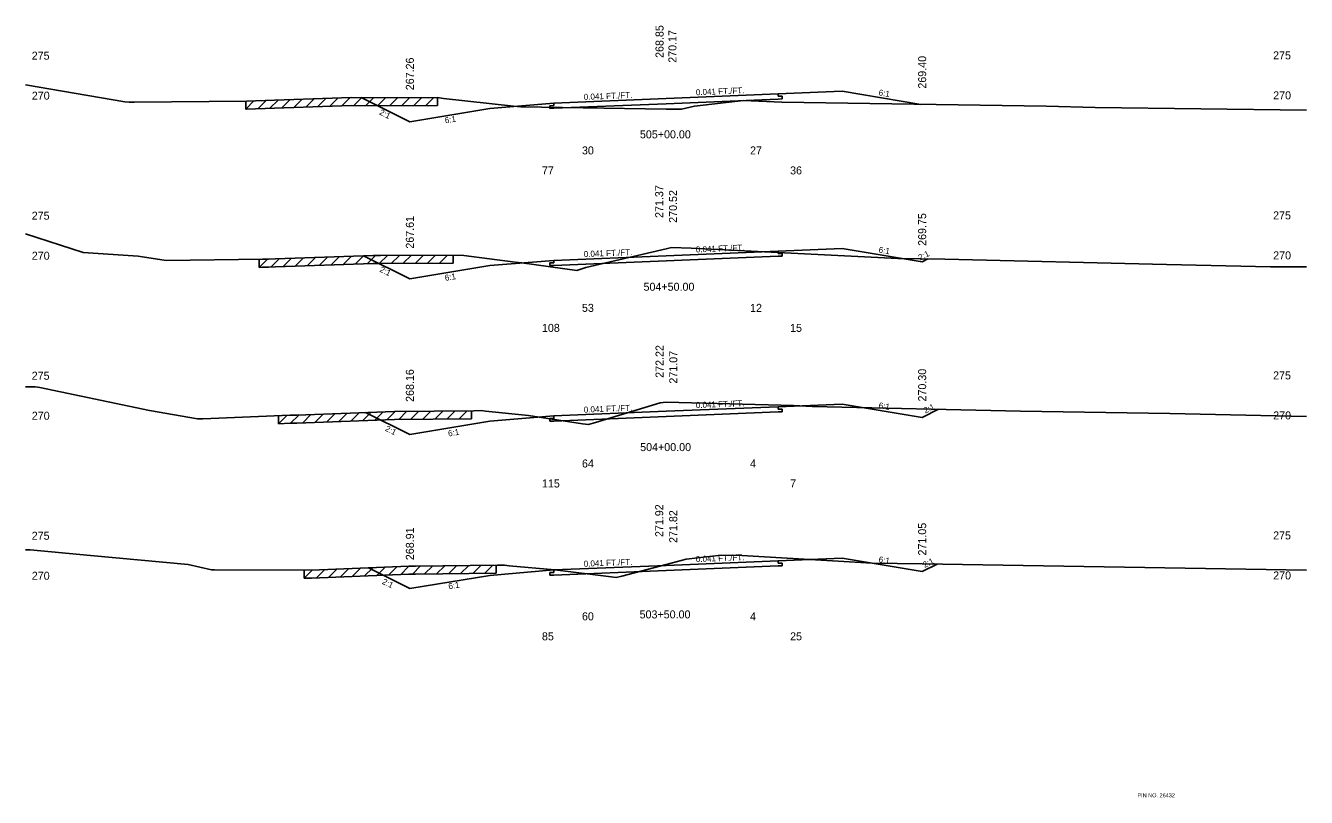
# Model space of a CAD drawing. Extents: x 2967 to 4323, y -3677 to -817.
# Drawn here: x 3188.8 to 3348.8, y -2657 to -2560.6 of the extents above; entities that cross this region are included whole.
import ezdxf

# ---------------------------------------------------------------- set-up
doc = ezdxf.new("R2010")
doc.units = 0
for name, color, linetype in [('Level 1', 7, 'Continuous'), ('Level 10', 7, 'Continuous'), ('Level 11', 7, 'Continuous'), ('Level 12', 7, 'Continuous'), ('Level 20', 7, 'Continuous'), ('Level 3', 7, 'Continuous'), ('Level 32', 7, 'Continuous'), ('Level 33', 7, 'Continuous'), ('Level 59', 7, 'Continuous'), ('Level 6', 7, 'Continuous'), ('Level 60', 7, 'Continuous'), ('Level 61', 7, 'Continuous'), ('Level 7', 7, 'Continuous')]:
    doc.layers.add(name, color=color, linetype=linetype)

msp = doc.modelspace()

# ---------------------------------------------------------------- linework, layer by layer
at = {"layer": 'Level 11'}
for p, q in [((3282.76, -2569.4), (3282.76, -2569.1)), ((3283.26, -2569.38), (3282.76, -2569.4)), ((3283.26, -2569.72), (3283.26, -2569.38)), ((3254.76, -2570.55), (3254.26, -2570.57)), ((3254.26, -2570.57), (3254.26, -2570.91)), ((3254.26, -2570.91), (3254.76, -2570.89)), ((3254.76, -2570.25), (3254.76, -2570.55)), ((3282.76, -2569.74), (3283.26, -2569.72)), ((3282.76, -2589.05), (3282.76, -2588.75)), ((3254.76, -2590.2), (3254.26, -2590.22)), ((3254.26, -2590.22), (3254.26, -2590.56)), ((3254.76, -2589.9), (3254.76, -2590.2)), ((3283.26, -2589.03), (3282.76, -2589.05)), ((3282.76, -2589.39), (3283.26, -2589.37)), ((3283.26, -2589.37), (3283.26, -2589.03)), ((3254.26, -2590.56), (3254.76, -2590.54)), ((3254.76, -2609.35), (3254.76, -2609.65)), ((3282.76, -2608.5), (3282.76, -2608.2)), ((3283.26, -2608.48), (3282.76, -2608.5)), ((3282.76, -2608.84), (3283.26, -2608.82)), ((3283.26, -2608.82), (3283.26, -2608.48)), ((3254.76, -2609.65), (3254.26, -2609.67)), ((3254.26, -2609.67), (3254.26, -2610.01)), ((3254.26, -2610.01), (3254.76, -2609.99)), ((3254.76, -2628.6), (3254.76, -2628.9)), ((3282.76, -2627.75), (3282.76, -2627.45)), ((3283.26, -2627.73), (3282.76, -2627.75)), ((3282.76, -2628.09), (3283.26, -2628.07)), ((3283.26, -2628.07), (3283.26, -2627.73)), ((3254.76, -2628.9), (3254.26, -2628.92)), ((3254.26, -2628.92), (3254.26, -2629.26)), ((3254.26, -2629.26), (3254.76, -2629.24))]:
    msp.add_line(p, q, dxfattribs=at)
at = {"layer": 'Level 12'}
for p, q in [((3268.76, -2570.32), (3254.76, -2570.89)), ((3282.76, -2569.74), (3268.76, -2570.32)), ((3268.76, -2589.96), (3254.76, -2590.54)), ((3282.76, -2589.39), (3268.76, -2589.96)), ((3268.76, -2609.41), (3254.76, -2609.99)), ((3282.76, -2608.84), (3268.76, -2609.41)), ((3268.76, -2628.67), (3254.76, -2629.24)), ((3282.76, -2628.09), (3268.76, -2628.67))]:
    msp.add_line(p, q, dxfattribs=at)
at = {"layer": 'Level 59'}
for p, q in [((3268.76, -2569.68), (3282.76, -2569.1)), ((3254.76, -2570.25), (3268.76, -2569.68)), ((3268.76, -2589.32), (3282.76, -2588.75)), ((3254.76, -2589.9), (3268.76, -2589.32)), ((3254.76, -2609.35), (3268.76, -2608.77)), ((3268.76, -2608.77), (3282.76, -2608.2)), ((3254.76, -2628.6), (3268.76, -2628.03)), ((3268.76, -2628.03), (3282.76, -2627.45))]:
    msp.add_line(p, q, dxfattribs=at)
at = {"layer": 'Level 6'}
for p, q in [((3282.76, -2569.1), (3290.76, -2568.77)), ((3246.76, -2570.92), (3254.76, -2570.25)), ((3282.76, -2588.75), (3290.76, -2588.42)), ((3246.76, -2590.56), (3254.76, -2589.9)), ((3282.76, -2608.2), (3290.76, -2607.87)), ((3246.76, -2610.01), (3254.76, -2609.35)), ((3282.76, -2627.45), (3290.76, -2627.12)), ((3246.76, -2629.27), (3254.76, -2628.6))]:
    msp.add_line(p, q, dxfattribs=at)
at = {"layer": 'Level 60'}
for p, q in [((3188.76, -2567.98), (3201.17, -2570.1)), ((3217.46, -2569.96), (3229.42, -2569.53)), ((3229.42, -2569.53), (3239.11, -2569.57)), ((3239.11, -2569.57), (3240.21, -2569.56)), ((3240.21, -2569.56), (3240.96, -2569.66)), ((3201.17, -2570.1), (3201.71, -2570.14)), ((3201.71, -2570.14), (3202.31, -2570.13)), ((3202.31, -2570.13), (3216.34, -2570)), ((3216.34, -2570), (3217.46, -2569.96)), ((3240.96, -2569.66), (3249.7, -2570.61)), ((3249.7, -2570.61), (3250.61, -2570.73)), ((3250.61, -2570.73), (3268.76, -2570.99)), ((3268.76, -2570.99), (3270.69, -2571.02)), ((3270.69, -2571.02), (3272.33, -2570.63)), ((3272.33, -2570.63), (3278.45, -2569.91)), ((3278.45, -2569.91), (3283.22, -2570.14)), ((3283.22, -2570.14), (3316.25, -2570.65)), ((3316.25, -2570.65), (3322.39, -2570.81)), ((3322.39, -2570.81), (3348.76, -2571.11)), ((3188.76, -2586.57), (3195.93, -2588.94)), ((3258.76, -2590.81), (3268.76, -2588.47)), ((3268.76, -2588.47), (3269.44, -2588.31)), ((3269.44, -2588.31), (3271.9, -2588.38)), ((3271.9, -2588.38), (3297.74, -2589.65)), ((3195.93, -2588.94), (3202.81, -2589.37)), ((3202.81, -2589.37), (3206.31, -2589.92)), ((3206.31, -2589.92), (3218.37, -2589.77)), ((3218.37, -2589.77), (3219.11, -2589.74)), ((3219.11, -2589.74), (3219.96, -2589.71)), ((3219.96, -2589.71), (3232.17, -2589.3)), ((3232.17, -2589.3), (3233.11, -2589.29)), ((3233.11, -2589.29), (3242.9, -2589.24)), ((3242.9, -2589.24), (3243.5, -2589.3)), ((3243.5, -2589.3), (3249.93, -2590.11)), ((3249.93, -2590.11), (3250.74, -2590.23)), ((3250.74, -2590.23), (3257.63, -2591.16)), ((3297.74, -2589.65), (3303.59, -2589.77)), ((3303.59, -2589.77), (3331.29, -2590.42)), ((3257.63, -2591.16), (3258.76, -2590.81)), ((3331.29, -2590.42), (3344.29, -2590.72)), ((3344.29, -2590.72), (3348.76, -2590.73)), ((3188.76, -2605.72), (3189.95, -2605.72)), ((3189.95, -2605.72), (3190.52, -2605.78)), ((3190.52, -2605.78), (3204.25, -2608.65)), ((3259.94, -2610.18), (3268.02, -2607.69)), ((3268.02, -2607.69), (3268.76, -2607.63)), ((3268.76, -2607.63), (3284.68, -2608.04)), ((3204.25, -2608.65), (3210.24, -2609.69)), ((3210.89, -2609.7), (3221.82, -2609.27)), ((3221.82, -2609.27), (3222.65, -2609.24)), ((3222.65, -2609.24), (3234.85, -2608.78)), ((3234.85, -2608.78), (3244.74, -2608.69)), ((3244.74, -2608.69), (3245.67, -2608.68)), ((3245.67, -2608.68), (3246.2, -2608.73)), ((3246.2, -2608.73), (3251.58, -2609.3)), ((3251.58, -2609.3), (3258.31, -2610.32)), ((3284.68, -2608.04), (3287.03, -2608.18)), ((3287.03, -2608.18), (3313.03, -2608.74)), ((3313.03, -2608.74), (3331.68, -2609.04)), ((3331.68, -2609.04), (3348.76, -2609.43)), ((3210.24, -2609.69), (3210.89, -2609.7)), ((3258.31, -2610.32), (3259.06, -2610.41)), ((3259.06, -2610.41), (3259.94, -2610.18)), ((3188.76, -2626.09), (3188.77, -2626.09)), ((3188.77, -2626.09), (3189.31, -2626.09)), ((3189.31, -2626.09), (3196.85, -2626.79)), ((3196.85, -2626.79), (3209.07, -2627.92)), ((3271.29, -2627.25), (3275.66, -2626.75)), ((3275.66, -2626.75), (3278.22, -2626.8)), ((3278.22, -2626.8), (3294.51, -2627.73)), ((3209.07, -2627.92), (3211.99, -2628.56)), ((3211.99, -2628.56), (3212.37, -2628.56)), ((3212.37, -2628.56), (3224.48, -2628.64)), ((3224.48, -2628.64), (3236.65, -2628.14)), ((3236.65, -2628.14), (3237.47, -2628.11)), ((3237.47, -2628.11), (3247.72, -2627.99)), ((3247.72, -2627.99), (3248.57, -2627.98)), ((3248.57, -2627.98), (3249.16, -2628.06)), ((3249.16, -2628.06), (3254.87, -2628.57)), ((3254.87, -2628.57), (3261.9, -2629.47)), ((3263.26, -2629.38), (3268.76, -2627.92)), ((3268.76, -2627.92), (3271.29, -2627.25)), ((3294.51, -2627.73), (3300.77, -2627.83)), ((3300.77, -2627.83), (3348.76, -2628.63)), ((3261.9, -2629.47), (3262.55, -2629.54)), ((3262.55, -2629.54), (3263.26, -2629.38))]:
    msp.add_line(p, q, dxfattribs=at)
at = {"layer": 'Level 61'}
for p, q in [((3227.79, -2569.59), (3226.75, -2570.63)), ((3229.29, -2569.54), (3228.25, -2570.57)), ((3230.75, -2569.54), (3229.75, -2570.53)), ((3232.25, -2569.54), (3231.26, -2570.54)), ((3233.75, -2569.55), (3232.76, -2570.54)), ((3235.25, -2569.55), (3234.26, -2570.55)), ((3236.75, -2569.56), (3235.76, -2570.55)), ((3238.25, -2569.56), (3237.26, -2570.56)), ((3239.76, -2569.56), (3238.76, -2570.56)), ((3240.23, -2570.56), (3240.23, -2569.56)), ((3217.28, -2569.97), (3216.25, -2571)), ((3216.25, -2570), (3216.25, -2571)), ((3216.25, -2571), (3216.34, -2571)), ((3216.34, -2571), (3217.46, -2570.96)), ((3217.46, -2570.96), (3229.42, -2570.53)), ((3218.79, -2569.92), (3217.75, -2570.95)), ((3220.29, -2569.86), (3219.25, -2570.9)), ((3221.79, -2569.81), (3220.75, -2570.84)), ((3223.29, -2569.75), (3222.25, -2570.79)), ((3224.79, -2569.7), (3223.75, -2570.74)), ((3226.29, -2569.64), (3225.25, -2570.68)), ((3229.42, -2570.53), (3239.11, -2570.57)), ((3239.11, -2570.57), (3240.21, -2570.56)), ((3240.21, -2570.56), (3240.23, -2570.56)), ((3218.96, -2589.75), (3217.93, -2590.78)), ((3217.93, -2589.78), (3217.93, -2590.78)), ((3220.47, -2589.69), (3219.43, -2590.73)), ((3219.96, -2590.71), (3232.17, -2590.3)), ((3221.97, -2589.64), (3220.93, -2590.68)), ((3223.47, -2589.59), (3222.43, -2590.63)), ((3224.97, -2589.54), (3223.93, -2590.58)), ((3226.47, -2589.49), (3225.44, -2590.53)), ((3227.97, -2589.44), (3226.94, -2590.47)), ((3229.47, -2589.39), (3228.44, -2590.42)), ((3230.97, -2589.34), (3229.94, -2590.37)), ((3232.47, -2589.3), (3231.44, -2590.32)), ((3232.17, -2590.3), (3233.11, -2590.29)), ((3233.95, -2589.29), (3232.94, -2590.29)), ((3233.11, -2590.29), (3242.16, -2590.24)), ((3235.45, -2589.28), (3234.44, -2590.28)), ((3236.95, -2589.27), (3235.94, -2590.27)), ((3238.45, -2589.26), (3237.45, -2590.27)), ((3239.95, -2589.25), (3238.95, -2590.26)), ((3241.45, -2589.24), (3240.45, -2590.25)), ((3242.16, -2590.24), (3242.16, -2589.24)), ((3217.93, -2590.78), (3218.37, -2590.77)), ((3218.37, -2590.77), (3219.11, -2590.74)), ((3219.11, -2590.74), (3219.96, -2590.71)), ((3221.4, -2609.29), (3220.36, -2610.33)), ((3220.36, -2609.33), (3220.36, -2610.33)), ((3222.91, -2609.23), (3221.86, -2610.27)), ((3224.41, -2609.17), (3223.37, -2610.21)), ((3225.91, -2609.12), (3224.87, -2610.16)), ((3227.41, -2609.06), (3226.37, -2610.1)), ((3228.91, -2609), (3227.87, -2610.04)), ((3230.42, -2608.95), (3229.38, -2609.99)), ((3231.92, -2608.89), (3230.88, -2609.93)), ((3233.42, -2608.83), (3232.38, -2609.87)), ((3234.92, -2608.78), (3233.88, -2609.82)), ((3236.4, -2608.77), (3235.39, -2609.78)), ((3237.9, -2608.75), (3236.89, -2609.76)), ((3239.4, -2608.74), (3238.39, -2609.75)), ((3240.9, -2608.73), (3239.89, -2609.74)), ((3242.41, -2608.71), (3241.4, -2609.72)), ((3243.91, -2608.7), (3242.9, -2609.71)), ((3244.47, -2609.7), (3244.47, -2608.7)), ((3220.36, -2610.33), (3221.82, -2610.27)), ((3221.82, -2610.27), (3222.65, -2610.24)), ((3222.65, -2610.24), (3234.85, -2609.78)), ((3234.85, -2609.78), (3244.47, -2609.7)), ((3224.55, -2628.64), (3223.55, -2629.64)), ((3223.55, -2628.64), (3223.55, -2629.64)), ((3226.1, -2628.58), (3225.06, -2629.62)), ((3227.61, -2628.52), (3226.56, -2629.56)), ((3229.11, -2628.45), (3228.06, -2629.5)), ((3230.61, -2628.39), (3229.57, -2629.43)), ((3232.12, -2628.33), (3231.07, -2629.37)), ((3233.62, -2628.27), (3232.58, -2629.31)), ((3235.12, -2628.21), (3234.08, -2629.25)), ((3236.63, -2628.14), (3235.58, -2629.19)), ((3238.11, -2628.1), (3237.09, -2629.13)), ((3239.61, -2628.09), (3238.59, -2629.1)), ((3241.11, -2628.07), (3240.09, -2629.08)), ((3242.61, -2628.05), (3241.6, -2629.06)), ((3244.12, -2628.03), (3243.1, -2629.04)), ((3245.62, -2628.02), (3244.61, -2629.03)), ((3247.12, -2628), (3246.11, -2629.01)), ((3247.54, -2628.99), (3247.54, -2627.99)), ((3223.55, -2629.64), (3224.48, -2629.64)), ((3224.48, -2629.64), (3236.65, -2629.14)), ((3236.65, -2629.14), (3237.47, -2629.11)), ((3237.47, -2629.11), (3247.54, -2628.99))]:
    msp.add_line(p, q, dxfattribs=at)
at = {"layer": 'Level 7'}
for p, q in [((3230.66, -2569.54), (3236.76, -2572.58)), ((3290.76, -2568.77), (3300.58, -2570.41)), ((3236.76, -2572.58), (3246.76, -2570.92)), ((3290.76, -2588.42), (3300.76, -2590.09)), ((3230.98, -2589.34), (3236.76, -2592.23)), ((3300.76, -2590.09), (3301.48, -2589.73)), ((3236.76, -2592.23), (3246.76, -2590.56)), ((3290.76, -2607.87), (3300.76, -2609.54)), ((3231.23, -2608.92), (3236.76, -2611.68)), ((3300.76, -2609.54), (3302.8, -2608.52)), ((3236.76, -2611.68), (3246.76, -2610.01)), ((3290.76, -2627.12), (3300.76, -2628.79)), ((3231.59, -2628.35), (3236.76, -2630.93)), ((3300.76, -2628.79), (3302.62, -2627.86)), ((3236.76, -2630.93), (3246.76, -2629.27))]:
    msp.add_line(p, q, dxfattribs=at)

# ---------------------------------------------------------------- texts
at = {"layer": 'Level 1'}
for s, p in [('30', (3258.26, -2576.66)), ('27', (3279.26, -2576.66)), ('77', (3253.26, -2579.16)), ('36', (3284.26, -2579.16)), ('53', (3258.26, -2596.34)), ('12', (3279.26, -2596.34)), ('108', (3253.26, -2598.84)), ('15', (3284.26, -2598.84)), ('64', (3258.26, -2615.79)), ('4', (3279.26, -2615.79)), ('115', (3253.26, -2618.29)), ('7', (3284.26, -2618.29)), ('60', (3258.26, -2634.89)), ('4', (3279.26, -2634.89)), ('85', (3253.26, -2637.39)), ('25', (3284.26, -2637.39))]:
    msp.add_text(s, height=1, dxfattribs=at).set_placement(p)
at = {"layer": 'Level 10'}
for s, p in [('268.85', (3268.45, -2564.6)), ('271.37', (3268.41, -2584.6)), ('272.22', (3268.45, -2604.58)), ('271.92', (3268.41, -2624.48))]:
    msp.add_text(s, height=1, rotation=90, dxfattribs=at).set_placement(p)
for s, p in [('505+00.00', (3265.5, -2574.65)), ('504+50.00', (3265.95, -2593.7)), ('504+00.00', (3265.53, -2613.74)), ('503+50.00', (3265.46, -2634.65))]:
    msp.add_text(s, height=1, dxfattribs=at).set_placement(p)
at = {"layer": 'Level 20'}
msp.add_text('PIN NO. 26432', height=0.5, dxfattribs=at).set_placement((3327.65, -2657.01))
at = {"layer": 'Level 3'}
for s, p in [(' 275', (3189.15, -2564.82)), (' 275', (3344.23, -2564.78)), (' 270', (3189.16, -2569.82)), (' 270', (3344.24, -2569.78)), (' 275', (3189.15, -2584.82)), (' 275', (3344.23, -2584.78)), (' 270', (3344.24, -2589.78)), (' 270', (3189.16, -2589.82)), (' 275', (3189.15, -2604.82)), (' 275', (3344.23, -2604.78)), (' 270', (3189.16, -2609.82)), (' 270', (3344.24, -2609.78)), (' 275', (3189.15, -2624.82)), (' 275', (3344.23, -2624.78)), (' 270', (3344.24, -2629.78)), (' 270', (3189.16, -2629.82))]:
    msp.add_text(s, height=1, dxfattribs=at).set_placement(p)
at = {"layer": 'Level 32'}
for s, rotation, p in [('0.041 FT./FT.', 2.3478, (3258.5, -2569.85)), ('0.041 FT./FT.', 2.3478, (3272.5, -2569.27)), ('6:1', 350.5377, (3295.28, -2569.27)), ('2:1', 333.435, (3232.87, -2571.63)), ('6:1', 9.4623, (3241.19, -2572.79)), ('0.041 FT./FT.', 2.3478, (3258.5, -2589.49)), ('0.041 FT./FT.', 2.3478, (3272.5, -2588.92)), ('6:1', 350.5377, (3295.28, -2588.92)), ('2:1', 26.5651, (3300.5, -2589.94)), ('2:1', 333.435, (3232.91, -2591.28)), ('6:1', 9.4623, (3241.19, -2592.47)), ('0.041 FT./FT.', 2.3478, (3258.5, -2608.94)), ('0.041 FT./FT.', 2.3478, (3272.5, -2608.37)), ('6:1', 350.5377, (3295.28, -2608.37)), ('2:1', 26.5651, (3301.16, -2609.06)), ('2:1', 333.435, (3233.6, -2611.17)), ('6:1', 9.4623, (3241.6, -2611.92)), ('0.041 FT./FT.', 2.3478, (3272.5, -2627.62)), ('6:1', 350.5377, (3295.28, -2627.62)), ('2:1', 26.5651, (3301.07, -2628.35)), ('0.041 FT./FT.', 2.3478, (3258.5, -2628.2)), ('2:1', 333.435, (3233.22, -2630.29)), ('6:1', 9.4623, (3241.64, -2631.02))]:
    msp.add_text(s, height=0.75, rotation=rotation, dxfattribs=at).set_placement(p)
at = {"layer": 'Level 33'}
for s, p in [('267.26', (3237.26, -2568.64)), ('269.40', (3301.26, -2568.44)), ('267.61', (3237.26, -2588.44)), ('269.75', (3301.26, -2588.09)), ('268.16', (3237.26, -2607.59)), ('270.30', (3301.26, -2607.54)), ('268.91', (3237.26, -2627.37)), ('271.05', (3301.26, -2626.79))]:
    msp.add_text(s, height=1, rotation=90, dxfattribs=at).set_placement(p)
at = {"layer": 'Level 59'}
for s, p in [(' 270.17', (3270.06, -2565.58)), (' 270.52', (3270.13, -2585.58)), (' 271.07', (3270.17, -2605.68)), (' 271.82', (3270.16, -2625.59))]:
    msp.add_text(s, height=1, rotation=90, dxfattribs=at).set_placement(p)

doc.saveas('drawing.dxf')
